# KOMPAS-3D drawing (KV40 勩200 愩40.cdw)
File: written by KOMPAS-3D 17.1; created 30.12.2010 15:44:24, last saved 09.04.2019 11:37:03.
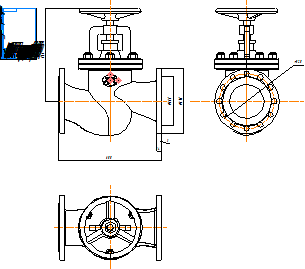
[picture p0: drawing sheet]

Title block, sheet 1: name: KV 40 Ду200; material: Внимание! Данный продукт является объектом авторского права ООО «Торговый Дом АДЛ». / Запрещается изменение, копирование, распространение / (в том числе путем копирования на другие сайты и ресурсы в Интернете) / или любое иное использование информации и объектов без предварительного / согласия правообладателя (ООО «Торговый Дом АДЛ»).; scale: 1:1; sheets: 1; organisation: ООО "Торговый дом АДЛ"; sheet format: A4; stored path: \\adlc.lan\data\АДЛ_ПКД\3D-модели\ADL production\Вентили ГРАНВЕНТ\KV40\KOMPAS 2D\KV 40 Ду200.cdw

Views: Спереди 1, Проекционный вид 2, Проекционный вид 3
Dimensions and other numbers on the sheet: 285; 375; 3; 34; 600; 540; 320; 1:1; 1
